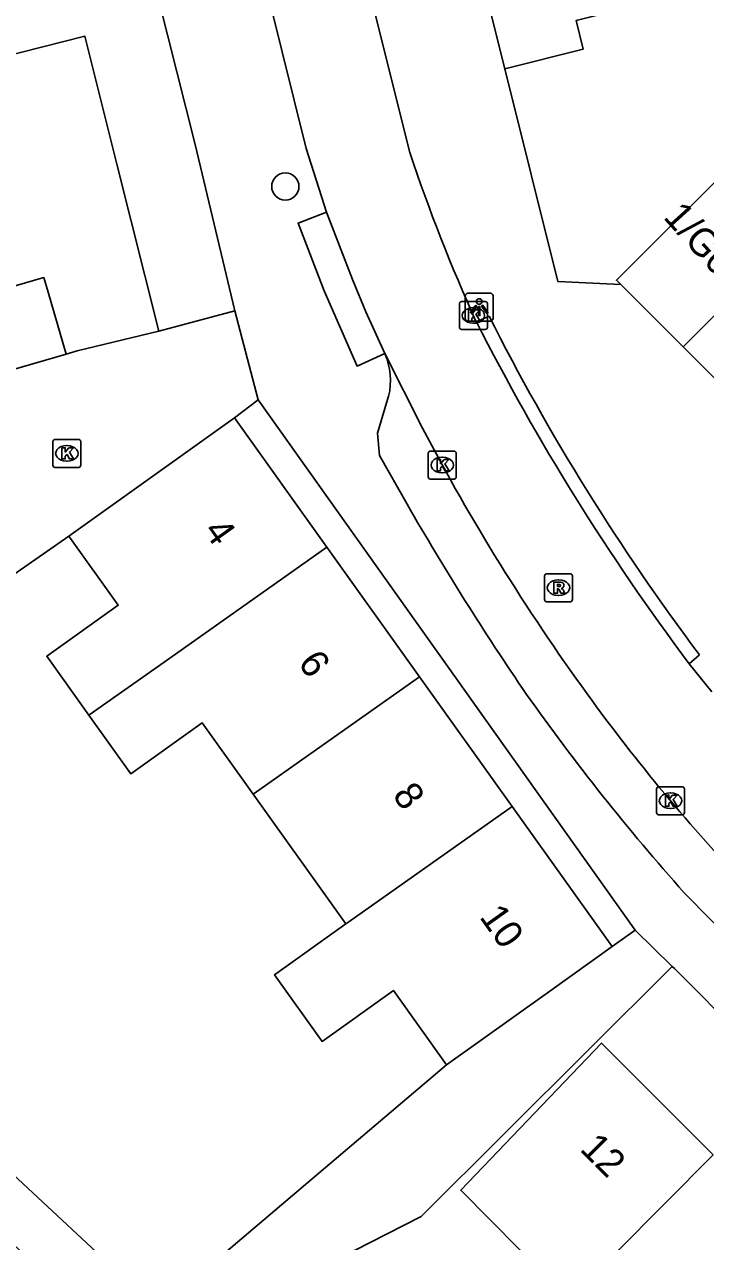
# Model space of a CAD drawing. Extents: x 162532 to 163264, y 381233 to 382042.
# Drawn here: x 162856.16 to 162880.58, y 381664.1 to 381707.72 of the extents above; entities that cross this region are included whole.
import ezdxf

# ---------------------------------------------------------------- set-up
doc = ezdxf.new("R2010")
doc.units = 0
for name, color, linetype in [('IMGEO_Boom', 7, 'Continuous'), ('IMGEO_Kolk', 7, 'Continuous'), ('IMGEO_Lichtpunt', 7, 'Continuous'), ('IMGEO_Muur', 7, 'Continuous'), ('IMGEO_Pand', 7, 'Continuous'), ('IMGEO_Pand_nummerreeks', 7, 'Continuous'), ('IMGEO_Rijbaan_lokaal_open', 7, 'Continuous'), ('IMGEO_Rioolput', 7, 'Continuous'), ('IMGEO_Voetpad_open', 7, 'Continuous')]:
    doc.layers.add(name, color=color, linetype=linetype)

msp = doc.modelspace()

# ---------------------------------------------------------------- linework, layer by layer
at = {"layer": 'IMGEO_Boom'}
msp.add_circle((162865.516, 381701.908), 0.489, dxfattribs=at)
at = {"layer": 'IMGEO_Kolk'}
for p, q in [((162871.756, 381696.86), (162871.756, 381697.712)), ((162871.831, 381697.786), (162872.683, 381697.786)), ((162872.757, 381697.712), (162872.757, 381696.86)), ((162872.244, 381697.566), (162872.269, 381697.566)), ((162872.683, 381696.786), (162871.831, 381696.786)), ((162872.267, 381697.006), (162872.242, 381697.006)), ((162857.186, 381691.918), (162857.186, 381692.77)), ((162857.261, 381692.844), (162858.113, 381692.844)), ((162857.674, 381692.624), (162857.699, 381692.624)), ((162858.187, 381692.77), (162858.187, 381691.918)), ((162870.714, 381692.425), (162871.566, 381692.425)), ((162857.697, 381692.064), (162857.672, 381692.064)), ((162870.639, 381691.499), (162870.639, 381692.351)), ((162871.127, 381692.205), (162871.152, 381692.205)), ((162871.64, 381692.351), (162871.64, 381691.499)), ((162858.113, 381691.844), (162857.261, 381691.844)), ((162871.15, 381691.645), (162871.125, 381691.645)), ((162871.566, 381691.425), (162870.714, 381691.425)), ((162878.819, 381679.474), (162878.819, 381680.326)), ((162878.894, 381680.4), (162879.746, 381680.4)), ((162879.82, 381680.326), (162879.82, 381679.474)), ((162879.307, 381680.18), (162879.332, 381680.18)), ((162879.746, 381679.4), (162878.894, 381679.4)), ((162879.33, 381679.62), (162879.305, 381679.62))]:
    msp.add_line(p, q, dxfattribs=at)
for points in [[(162871.756, 381696.86), (162871.756, 381697.712)], [(162871.831, 381697.786), (162872.683, 381697.786)], [(162872.757, 381697.712), (162872.757, 381696.86)], [(162872.077, 381697.486), (162872.2, 381697.486), (162872.2, 381697.335), (162872.33, 381697.486), (162872.494, 381697.486), (162872.348, 381697.335), (162872.501, 381697.086), (162872.349, 381697.086), (162872.264, 381697.25), (162872.2, 381697.183), (162872.2, 381697.086), (162872.077, 381697.086), (162872.077, 381697.486)], [(162872.683, 381696.786), (162871.831, 381696.786)], [(162857.186, 381691.918), (162857.186, 381692.77)], [(162857.261, 381692.844), (162858.113, 381692.844)], [(162857.507, 381692.544), (162857.63, 381692.544), (162857.63, 381692.393), (162857.76, 381692.544), (162857.924, 381692.544), (162857.778, 381692.393), (162857.931, 381692.144), (162857.779, 381692.144), (162857.694, 381692.308), (162857.63, 381692.241), (162857.63, 381692.144), (162857.507, 381692.144), (162857.507, 381692.544)], [(162858.187, 381692.77), (162858.187, 381691.918)], [(162870.714, 381692.425), (162871.566, 381692.425)], [(162870.639, 381691.499), (162870.639, 381692.351)], [(162870.96, 381692.125), (162871.083, 381692.125), (162871.083, 381691.974), (162871.213, 381692.125), (162871.377, 381692.125), (162871.231, 381691.974), (162871.384, 381691.725), (162871.232, 381691.725), (162871.147, 381691.889), (162871.083, 381691.822), (162871.083, 381691.725), (162870.96, 381691.725), (162870.96, 381692.125)], [(162871.64, 381692.351), (162871.64, 381691.499)], [(162858.113, 381691.844), (162857.261, 381691.844)], [(162871.566, 381691.425), (162870.714, 381691.425)], [(162878.819, 381679.474), (162878.819, 381680.326)], [(162878.894, 381680.4), (162879.746, 381680.4)], [(162879.82, 381680.326), (162879.82, 381679.474)], [(162879.14, 381680.1), (162879.263, 381680.1), (162879.263, 381679.949), (162879.393, 381680.1), (162879.557, 381680.1), (162879.411, 381679.949), (162879.564, 381679.7), (162879.412, 381679.7), (162879.327, 381679.864), (162879.263, 381679.797), (162879.263, 381679.7), (162879.14, 381679.7), (162879.14, 381680.1)], [(162879.746, 381679.4), (162878.894, 381679.4)]]:
    msp.add_lwpolyline(points, dxfattribs=at)
for centre, start, end in [((162871.833, 381697.71), 91.552, 178.448), ((162871.833, 381697.71), 91.552, 178.448), ((162872.681, 381697.71), 1.552, 88.448), ((162872.681, 381697.71), 1.552, 88.448), ((162871.833, 381696.862), 181.552, 268.448), ((162871.833, 381696.862), 181.552, 268.448), ((162872.681, 381696.862), 271.552, 358.448), ((162872.681, 381696.862), 271.552, 358.448), ((162857.263, 381692.768), 91.552, 178.448), ((162857.263, 381692.768), 91.552, 178.448), ((162858.111, 381692.768), 1.552, 88.448), ((162858.111, 381692.768), 1.552, 88.448), ((162870.716, 381692.349), 91.552, 178.448), ((162870.716, 381692.349), 91.552, 178.448), ((162871.564, 381692.349), 1.552, 88.448), ((162871.564, 381692.349), 1.552, 88.448), ((162857.263, 381691.92), 181.552, 268.448), ((162857.263, 381691.92), 181.552, 268.448), ((162858.111, 381691.92), 271.552, 358.448), ((162858.111, 381691.92), 271.552, 358.448), ((162870.716, 381691.501), 181.552, 268.448), ((162870.716, 381691.501), 181.552, 268.448), ((162871.564, 381691.501), 271.552, 358.448), ((162871.564, 381691.501), 271.552, 358.448), ((162878.896, 381680.324), 91.552, 178.448), ((162878.896, 381680.324), 91.552, 178.448), ((162879.744, 381680.324), 1.552, 88.448), ((162879.744, 381680.324), 1.552, 88.448), ((162878.896, 381679.476), 181.552, 268.448), ((162878.896, 381679.476), 181.552, 268.448), ((162879.744, 381679.476), 271.552, 358.448), ((162879.744, 381679.476), 271.552, 358.448)]:
    msp.add_arc(centre, 0.0765, start, end, dxfattribs=at)
for centre, major_axis, ratio, start_param, end_param in [((162872.243, 381697.286), (-0.387, 0.002), 0.722429, 4.712389, 7.853982), ((162872.268, 381697.286), (-0.39, 0.002), 0.717154, 1.570796, 4.712389), ((162857.673, 381692.344), (-0.387, 0.002), 0.722429, 4.712389, 7.853982), ((162857.698, 381692.344), (-0.39, 0.002), 0.717154, 1.570796, 4.712389), ((162871.126, 381691.925), (-0.387, 0.002), 0.722429, 4.712389, 7.853982), ((162871.151, 381691.925), (-0.39, 0.002), 0.717154, 1.570796, 4.712389), ((162879.306, 381679.9), (-0.387, 0.002), 0.722429, 4.712389, 7.853982), ((162879.331, 381679.9), (-0.39, 0.002), 0.717154, 1.570796, 4.712389)]:
    msp.add_ellipse(centre, major_axis=major_axis, ratio=ratio, start_param=start_param, end_param=end_param, dxfattribs=at)
at = {"layer": 'IMGEO_Lichtpunt'}
for p, q in [((162871.965, 381697.988), (162871.965, 381697.181)), ((162871.965, 381697.988), (162871.965, 381697.181)), ((162872.867, 381698.083), (162872.059, 381698.083)), ((162872.867, 381698.083), (162872.059, 381698.083)), ((162872.961, 381697.181), (162872.961, 381697.988)), ((162872.961, 381697.181), (162872.961, 381697.988)), ((162872.059, 381697.087), (162872.867, 381697.087)), ((162872.059, 381697.087), (162872.867, 381697.087))]:
    msp.add_line(p, q, dxfattribs=at)
for points in [[(162872.339, 381697.652), (162872.378, 381697.624), (162872.19, 381697.362), (162872.152, 381697.389), (162872.339, 381697.652)], [(162872.441, 381697.604), (162872.488, 381697.604), (162872.488, 381697.282), (162872.441, 381697.282), (162872.441, 381697.604)], [(162872.551, 381697.624), (162872.589, 381697.651), (162872.776, 381697.389), (162872.737, 381697.361), (162872.551, 381697.624)]]:
    msp.add_lwpolyline(points, dxfattribs=at)
msp.add_circle((162872.464, 381697.786), 0.0994, dxfattribs=at)
for centre, start, end in [((162872.059, 381697.988), 90, 180), ((162872.059, 381697.988), 90, 180), ((162872.867, 381697.988), 0, 90), ((162872.867, 381697.988), 0, 90), ((162872.059, 381697.181), 180, 270), ((162872.059, 381697.181), 180, 270), ((162872.867, 381697.181), 270, 0), ((162872.867, 381697.181), 270, 360)]:
    msp.add_arc(centre, 0.0946, start, end, dxfattribs=at)
at = {"layer": 'IMGEO_Muur'}
msp.add_lwpolyline([(162873.378, 381706.128), (162875.282, 381698.509), (162877.536, 381698.393)], dxfattribs=at)
at = {"layer": 'IMGEO_Pand'}
for points in [[(162873.378, 381706.128), (162870.429, 381717.925)], [(162859.316, 381715.205), (162862.283, 381703.406), (162863.706, 381697.45)], [(162879.301, 381708.696), (162875.937, 381707.854), (162876.192, 381706.832), (162873.378, 381706.128)], [(162860.98, 381696.726), (162859.481, 381702.701), (162858.326, 381707.293), (162855.261, 381706.522)], [(162877.536, 381698.393), (162877.384, 381698.545), (162881.859, 381703.023), (162882.011, 381702.871), (162884.246, 381700.642)], [(162884.246, 381700.642), (162879.774, 381696.157)], [(162851.513, 381697.093), (162856.861, 381698.646), (162857.016, 381698.115), (162857.66, 381695.9)], [(162879.774, 381696.157), (162877.536, 381698.393)], [(162860.98, 381696.726), (162863.706, 381697.45)], [(162882.007, 381693.926), (162879.774, 381696.157)], [(162852.217, 381694.321), (162857.66, 381695.9)], [(162863.693, 381693.62), (162857.763, 381689.381)], [(162863.693, 381693.62), (162867.006, 381688.986)], [(162858.476, 381682.966), (162856.968, 381685.075), (162859.531, 381686.906), (162857.763, 381689.381)], [(162867.006, 381688.986), (162861.173, 381684.87), (162858.476, 381682.966)], [(162870.327, 381684.34), (162867.006, 381688.986)], [(162864.367, 381680.134), (162864.48, 381680.214), (162870.327, 381684.34)], [(162870.327, 381684.34), (162873.647, 381679.695)], [(162858.476, 381682.966), (162859.982, 381680.86), (162862.542, 381682.69), (162864.367, 381680.134)], [(162867.686, 381675.487), (162864.367, 381680.134)], [(162873.647, 381679.695), (162867.787, 381675.558), (162867.686, 381675.487)], [(162877.234, 381674.678), (162873.647, 381679.695)], [(162867.686, 381675.487), (162865.128, 381673.66), (162866.831, 381671.278), (162869.388, 381673.104), (162871.296, 381670.433)], [(162871.296, 381670.433), (162874.994, 381673.077), (162877.234, 381674.678)], [(162873.491, 381659.806), (162871.713, 381661.587), (162873.922, 381663.812), (162871.8, 381665.947), (162873.391, 381667.608), (162876.85, 381671.218), (162880.849, 381667.213)], [(162873.491, 381659.806), (162875.617, 381661.946), (162880.849, 381667.213)], [(162855.414, 381666.826), (162859.622, 381662.919), (162858.404, 381661.606), (162853.868, 381665.734)]]:
    msp.add_lwpolyline(points, dxfattribs=at)
at = {"layer": 'IMGEO_Rijbaan_lokaal_open'}
for points in [[(162866.25, 381718.01), (162869.978, 381703.121)], [(162866.993, 381700.988), (162866.267, 381703.263), (162862.821, 381717.136)], [(162866.993, 381700.988), (162867.919, 381698.57), (162868.405, 381697.414), (162869.078, 381695.924)], [(162863.706, 381697.45), (162864.542, 381694.268)], [(162857.66, 381695.9), (162858.051, 381696.014), (162860.98, 381696.726)], [(162870.434, 381693.246), (162869.078, 381695.924)], [(162864.542, 381694.268), (162863.693, 381693.62)], [(162857.763, 381689.381), (162846.118, 381681.283)], [(162879.988, 381684.807), (162880.801, 381683.802)]]:
    msp.add_lwpolyline(points, dxfattribs=at)
for centre, radius, start, end in [((162928.279, 381722.527), 61.446, 198.41082, 204.48991), ((162947.484, 381735.333), 84.312, 207.00011, 216.81789), ((162939.033, 381729.183), 77.442, 207.64886, 215.94219), ((162929.777, 381722.35), 65.938, 215.85611, 223.72748)]:
    msp.add_arc(centre, radius, start, end, dxfattribs=at)
at = {"layer": 'IMGEO_Rioolput'}
for p, q in [((162874.805, 381687.106), (162874.805, 381687.958)), ((162874.88, 381688.032), (162875.732, 381688.032)), ((162875.293, 381687.812), (162875.318, 381687.812)), ((162875.806, 381687.958), (162875.806, 381687.106)), ((162875.316, 381687.252), (162875.291, 381687.252)), ((162875.732, 381687.032), (162874.88, 381687.032))]:
    msp.add_line(p, q, dxfattribs=at)
for points in [[(162874.805, 381687.106), (162874.805, 381687.958)], [(162874.88, 381688.032), (162875.732, 381688.032)], [(162875.394, 381687.73), (162875.142, 381687.732), (162875.142, 381687.332)], [(162875.32, 381687.651), (162875.266, 381687.651), (162875.266, 381687.57)], [(162875.806, 381687.958), (162875.806, 381687.106)], [(162875.142, 381687.332), (162875.266, 381687.332), (162875.266, 381687.494), (162875.277, 381687.494)], [(162875.266, 381687.57), (162875.318, 381687.57)], [(162875.324, 381687.465), (162875.395, 381687.332), (162875.535, 381687.332), (162875.47, 381687.458)], [(162875.732, 381687.032), (162874.88, 381687.032)]]:
    msp.add_lwpolyline(points, dxfattribs=at)
for centre, radius, start, end in [((162874.882, 381687.956), 0.0765, 91.552, 178.448), ((162874.882, 381687.956), 0.0765, 91.552, 178.448), ((162875.326, 381687.555), 0.0964, 77.0061, 93.1865), ((162875.34, 381687.612), 0.0378, 276.6634, 79.6772), ((162875.393, 381687.62), 0.109, 350.3612, 89.416), ((162875.73, 381687.956), 0.0765, 1.552, 88.448), ((162875.73, 381687.956), 0.0765, 1.552, 88.448), ((162875.276, 381687.441), 0.0533, 26.0293, 88.6989), ((162875.302, 381687.759), 0.19, 274.7715, 282.9687), ((162875.391, 381687.62), 0.112, 277.5842, 350.9817), ((162875.375, 381687.405), 0.108, 29.5134, 73.7905), ((162874.882, 381687.108), 0.0765, 181.552, 268.448), ((162874.882, 381687.108), 0.0765, 181.552, 268.448), ((162875.73, 381687.108), 0.0765, 271.552, 358.448), ((162875.73, 381687.108), 0.0765, 271.552, 358.448)]:
    msp.add_arc(centre, radius, start, end, dxfattribs=at)
for centre, major_axis, ratio, start_param, end_param in [((162875.292, 381687.532), (-0.387, 0.002), 0.722429, 4.712389, 7.853982), ((162875.317, 381687.532), (-0.39, 0.002), 0.717154, 1.570796, 4.712389)]:
    msp.add_ellipse(centre, major_axis=major_axis, ratio=ratio, start_param=start_param, end_param=end_param, dxfattribs=at)
at = {"layer": 'IMGEO_Voetpad_open'}
for points in [[(162877.536, 381698.393), (162875.282, 381698.509), (162873.378, 381706.128)], [(162869.078, 381695.924), (162868.085, 381695.475), (162866.907, 381698.164), (162865.975, 381700.598), (162866.993, 381700.988)], [(162872.361, 381697.056), (162872.821, 381697.261)], [(162864.542, 381694.268), (162878.048, 381675.26)], [(162869.878, 381690.523), (162868.892, 381692.273), (162868.818, 381693.065), (162869.217, 381694.392)], [(162840.567, 381689.245), (162833.97, 381687.029), (162840.83, 381677.561), (162841.654, 381676.737), (162841.55, 381676.625), (162844.979, 381673.441), (162849.256, 381669.47), (162853.533, 381665.498), (162859.126, 381660.304), (162860.659, 381661.956), (162861.989, 381662.547), (162871.296, 381670.433)], [(162880.358, 381685.133), (162879.988, 381684.807)], [(162884.745, 381671.613), (162879.809, 381676.605)], [(162877.234, 381674.678), (162878.048, 381675.26)], [(162878.048, 381675.26), (162879.384, 381673.963)], [(162879.384, 381673.963), (162870.387, 381665.005), (162862.578, 381661.026), (162862.266, 381660.774)], [(162915.574, 381636.334), (162916.21, 381636.979), (162879.464, 381673.885), (162879.384, 381673.963)]]:
    msp.add_lwpolyline(points, dxfattribs=at)
for centre, radius, start, end in [((162944.143, 381733.179), 79.856, 206.72963, 216.98851), ((162866.891, 381694.953), 2.393, 346.4358, 23.9329), ((162962.424, 381743.954), 106.863, 209.99984, 214.3144), ((162940.572, 381730.701), 81.354, 215.28087, 221.67801)]:
    msp.add_arc(centre, radius, start, end, dxfattribs=at)

# ---------------------------------------------------------------- texts
at = {"layer": 'IMGEO_Pand_nummerreeks'}
for s, rotation, p in [('1/G01', 312.1351, (162879.03, 381700.789)), ('4', 305.5597, (162862.557, 381689.569)), ('6', 305.5576, (162865.942, 381684.833)), ('8', 305.5597, (162869.33, 381680.094)), ('10', 305.5597, (162872.447, 381675.734)), ('12', 314.9559, (162876.037, 381667.39))]:
    msp.add_text(s, height=1, rotation=rotation, dxfattribs=at).set_placement(p)

doc.saveas('drawing.dxf')
